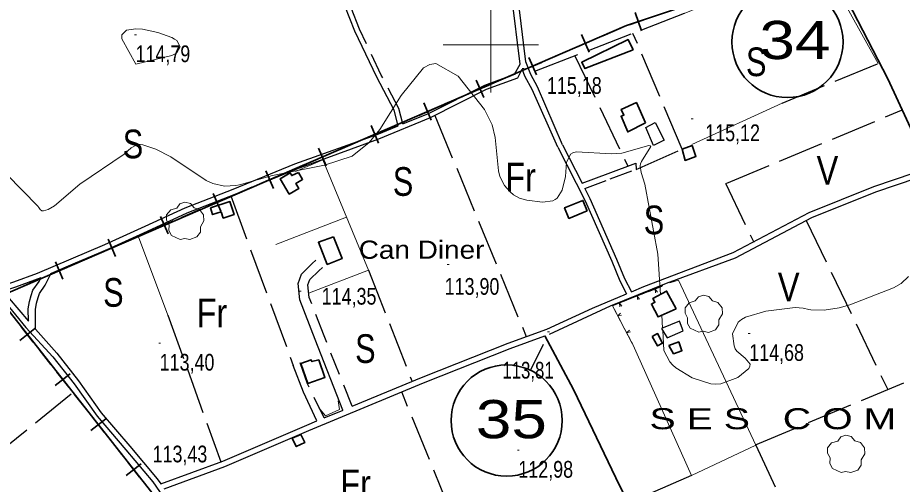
# Model space of a CAD drawing. Extents: x 483840 to 488445, y 4386047 to 4389027.
# Drawn here: x 484752.4 to 485215.3, y 4388270 to 4388514.2 of the extents above; entities that cross this region are included whole.
import ezdxf
from ezdxf.enums import TextEntityAlignment as Align

# ---------------------------------------------------------------- set-up
doc = ezdxf.new("R2010")
doc.units = 0
doc.header["$LTSCALE"] = 4
doc.linetypes.add('LONG_DASHED', pattern=[7.5, 6, -1.5])
doc.linetypes.add('MEDIUM_DASHED', pattern=[4.5, 3, -1.5])
for name, color, linetype, lineweight in [('1', 7, 'Continuous', 13), ('13', 7, 'Continuous', 25), ('21', 7, 'Continuous', 25), ('24', 7, 'Continuous', 13), ('25', 7, 'LONG_DASHED', 25), ('29', 7, 'Continuous', 13), ('34', 7, 'Continuous', 35), ('38', 7, 'Continuous', 25), ('47', 7, 'Continuous', 35), ('51', 7, 'Continuous', 13), ('6', 7, 'Continuous', 35), ('7', 7, 'Continuous', 13), ('9', 7, 'Continuous', 13)]:
    doc.layers.add(name, color=color, linetype=linetype, lineweight=lineweight)
doc.layers.add('31', color=7, linetype='Continuous')
doc.layers.add('5', color=7, linetype='Continuous')

msp = doc.modelspace()

# ---------------------------------------------------------------- linework, layer by layer
at = {"layer": '1'}
for p, q in [((485000, 4388525), (485000, 4388475)), ((484975, 4388500), (485025, 4388500))]:
    msp.add_line(p, q, dxfattribs=at)
at = {"layer": '21'}
for points in [[(485085.2, 4388447.27), (485081.2, 4388456.64), (485086.08, 4388459.28), (485090.67, 4388450.06)], [(485092.34, 4388346.69), (485100.66, 4388350.31), (485098.7, 4388355.4), (485089.4, 4388351.49)]]:
    msp.add_lwpolyline(points, close=True, dxfattribs=at)
at = {"layer": '24'}
for p, q in [((485082.46, 4388370.8), (485089.44, 4388373.55)), ((485063.87, 4388363.49), (485070.85, 4388366.24)), ((485073.17, 4388367.15), (485080.15, 4388369.89)), ((485068.18, 4388354.79), (485064.67, 4388361.42)), ((485072.85, 4388345.96), (485069.34, 4388352.59))]:
    msp.add_line(p, q, dxfattribs=at)
for points in [[(485074.01, 4388343.76), (485063.63, 4388363.4), (485090.09, 4388373.8)], [(485087.19, 4388370.51), (485085.95, 4388372.17), (485086.19, 4388370.12)], [(485077.89, 4388366.86), (485076.66, 4388368.52), (485076.89, 4388366.46)], [(485068.59, 4388363.2), (485067.36, 4388364.87), (485067.6, 4388362.81)], [(485067.94, 4388359.52), (485066.43, 4388358.11), (485068.44, 4388358.58)], [(485072.61, 4388350.69), (485071.09, 4388349.28), (485073.11, 4388349.74)]]:
    msp.add_lwpolyline(points, dxfattribs=at)
at = {"layer": '25'}
for p, q in [((485101.21, 4388516.39), (485020.66, 4388485.07)), ((485044.03, 4388494.16), (485071.69, 4388436.47)), ((485152.45, 4388469.44), (485202.67, 4388490.24)), ((484970.7, 4388463.07), (485018.53, 4388347.26)), ((485123.43, 4388427.6), (485214.94, 4388465.75)), ((485122.74, 4388427.51), (485137.62, 4388396.72)), ((484863.91, 4388420.9), (484896.65, 4388332.19)), ((485165.03, 4388408.01), (485207.74, 4388319.56)), ((484935.95, 4388382.07), (484958.8, 4388323.76)), ((484831.04, 4388358.42), (484858.7, 4388281.74)), ((485138.58, 4388290.73), (485276.3, 4388348.15)), ((484691.81, 4388245.64), (484783.75, 4388320)), ((485104.98, 4388274.62), (485074.29, 4388261.26))]:
    msp.add_line(p, q, dxfattribs=at)
for points in [[(485075.91, 4388438.03), (485076.01, 4388434.79), (485100.13, 4388445.35), (485074.4, 4388505.97)], [(484870.29, 4388214.84), (484979.22, 4388255.21), (484953.38, 4388318.33)], [(485138.71, 4388290.43), (485159.41, 4388245.83), (485093.48, 4388220.32)]]:
    msp.add_lwpolyline(points, dxfattribs=at)
at = {"layer": '29'}
for points in [[(484837.52, 4388398.15), (484832.98, 4388400.27), (484831.57, 4388402.81), (484831.67, 4388405.79), (484830.3, 4388408.2), (484830.34, 4388410.95), (484832.5, 4388413.55), (484835.69, 4388414.55), (484837.34, 4388416.74), (484839.91, 4388417.57), (484842.77, 4388416.92), (484844.72, 4388414.65), (484847.53, 4388413.83), (484849.66, 4388410.98), (484849.9, 4388407.85), (484848.02, 4388404.7), (484848.02, 4388402.02), (484846.2, 4388399.41), (484842.58, 4388398.07), (484839.81, 4388398.7)], [(485108.85, 4388349.53), (485104.31, 4388351.65), (485102.9, 4388354.19), (485103, 4388357.17), (485101.63, 4388359.58), (485101.67, 4388362.33), (485103.83, 4388364.93), (485107.02, 4388365.93), (485108.67, 4388368.12), (485111.24, 4388368.95), (485114.1, 4388368.3), (485116.05, 4388366.03), (485118.86, 4388365.21), (485120.99, 4388362.36), (485121.23, 4388359.23), (485119.35, 4388356.08), (485119.35, 4388353.4), (485117.53, 4388350.79), (485113.91, 4388349.45), (485111.14, 4388350.08)], [(485183.38, 4388276.22), (485178.84, 4388278.34), (485177.43, 4388280.88), (485177.53, 4388283.86), (485176.16, 4388286.27), (485176.2, 4388289.02), (485178.36, 4388291.62), (485181.55, 4388292.62), (485183.2, 4388294.81), (485185.77, 4388295.64), (485188.63, 4388294.99), (485190.58, 4388292.72), (485193.39, 4388291.9), (485195.52, 4388289.05), (485195.76, 4388285.92), (485193.88, 4388282.77), (485193.88, 4388280.09), (485192.06, 4388277.48), (485188.44, 4388276.14), (485185.67, 4388276.77)]]:
    msp.add_lwpolyline(points, close=True, dxfattribs=at)
at = {"layer": '34'}
for p, q in [((485072.45, 4388510.49), (485081.93, 4388513.67)), ((485075.6, 4388516.82), (485078.79, 4388507.34)), ((485047.48, 4388505.3), (485051.45, 4388496.11)), ((485058.65, 4388504.67), (485067.83, 4388508.63)), ((485044.87, 4388498.72), (485054.05, 4388502.69)), ((485031.11, 4388492.78), (485040.29, 4388496.75)), ((485017.34, 4388486.84), (485026.52, 4388490.8)), ((485019.95, 4388493.41), (485023.91, 4388484.23)), ((484992.41, 4388481.53), (484996.38, 4388472.35)), ((485003.58, 4388480.9), (485012.76, 4388484.86)), ((484989.8, 4388474.95), (484998.99, 4388478.92)), ((484976.04, 4388469.01), (484985.22, 4388472.98)), ((484964.88, 4388469.64), (484968.84, 4388460.46)), ((484962.27, 4388463.07), (484971.45, 4388467.03)), ((484948.51, 4388457.13), (484957.69, 4388461.09)), ((484934.73, 4388451.19), (484943.92, 4388455.15)), ((484937.34, 4388457.76), (484941.31, 4388448.58)), ((484920.97, 4388445.25), (484930.15, 4388449.21)), ((484909.81, 4388445.87), (484913.77, 4388436.69)), ((484907.2, 4388439.3), (484916.38, 4388443.26)), ((484893.44, 4388433.36), (484902.62, 4388437.32)), ((484879.66, 4388427.42), (484888.85, 4388431.38)), ((484882.27, 4388433.99), (484886.24, 4388424.81)), ((484854.74, 4388422.11), (484858.7, 4388412.92)), ((484865.9, 4388421.48), (484875.08, 4388425.44)), ((484852.13, 4388415.53), (484861.31, 4388419.5)), ((484838.37, 4388409.59), (484847.55, 4388413.56)), ((484824.6, 4388403.65), (484833.78, 4388407.61)), ((484827.2, 4388410.22), (484831.17, 4388401.04)), ((484799.67, 4388398.34), (484803.63, 4388389.16)), ((484810.83, 4388397.71), (484820.01, 4388401.67)), ((484797.06, 4388391.76), (484806.24, 4388395.73)), ((484783.3, 4388385.82), (484792.48, 4388389.79)), ((484772.13, 4388386.45), (484776.1, 4388377.27)), ((484769.53, 4388379.88), (484778.71, 4388383.84)), ((484755.76, 4388373.94), (484764.94, 4388377.9)), ((484754.37, 4388352.29), (484760.56, 4388344.43)), ((484753.54, 4388345.27), (484761.39, 4388351.45)), ((484763.65, 4388340.5), (484769.84, 4388332.65)), ((484772.93, 4388328.72), (484779.12, 4388320.86)), ((484772.1, 4388321.7), (484779.95, 4388327.88)), ((484782.21, 4388316.93), (484788.4, 4388309.08)), ((484790.66, 4388298.13), (484798.52, 4388304.31)), ((484791.49, 4388305.15), (484797.68, 4388297.29)), ((484800.77, 4388293.36), (484806.96, 4388285.51)), ((484809.22, 4388274.56), (484817.08, 4388280.74)), ((484810.05, 4388281.58), (484816.24, 4388273.72))]:
    msp.add_line(p, q, dxfattribs=at)
for points in [[(484742, 4388368), (485071, 4388510), (485202, 4388554), (485338, 4388632), (485442, 4388724), (485439, 4388753), (485444.8, 4388757.76)], [(484742, 4388368), (484968, 4388081), (484988, 4388018), (485030, 4387786), (485030, 4387747), (484843, 4387760), (484712, 4387762), (484623, 4387793), (484342, 4387807), (484273, 4387819), (484108.44, 4387807.03)]]:
    msp.add_lwpolyline(points, dxfattribs=at)
at = {"layer": '38'}
for p, q in [((484940.47, 4388453.04), (484951.52, 4388457.57)), ((485037.47, 4388447.58), (485047.74, 4388427.5)), ((484912.8, 4388304.73), (484922.8, 4388308.87))]:
    msp.add_line(p, q, dxfattribs=at)
for points in [[(485015.38, 4388489.87), (485011.07, 4388525.18), (485005.15, 4388568.67), (485000, 4388598.29), (484999.53, 4388606.46), (484999.68, 4388610.36), (485000.57, 4388615.38), (485001.38, 4388623.79), (485001.37, 4388629.5), (484995.99, 4388665.8), (484982.61, 4388725.27), (484977.67, 4388757.77)], [(484951.52, 4388457.57), (484949.39, 4388465.73), (484940.36, 4388482.97), (484928.92, 4388507.18), (484918.37, 4388533.79), (484904.08, 4388555.37), (484899.78, 4388573.59), (484895.33, 4388588.74), (484890.42, 4388611.54), (484888.38, 4388617.01)], [(485037.47, 4388447.58), (485024.35, 4388478.07), (485020.87, 4388484.49), (485018.37, 4388491.05), (485014.15, 4388525.57), (485008.22, 4388569.14), (485003.09, 4388598.65), (485002.64, 4388606.49), (485002.78, 4388610.02), (485003.29, 4388612.91)], [(484941.37, 4388450.83), (484968.46, 4388461.94), (484997.8, 4388476.74), (485014.06, 4388482.67), (485016.47, 4388487.3)], [(484953.97, 4388458.58), (484967.47, 4388464.11), (484996.85, 4388478.93), (485012.37, 4388484.59), (485015.38, 4388489.87)], [(485035.03, 4388446.34), (485021.57, 4388476.67), (485018.04, 4388483.19), (485016.47, 4388487.3)], [(484741.2, 4388372.81), (484750.44, 4388375.99), (484762.7, 4388380.54), (484780.4, 4388387.97), (484798.05, 4388395.48), (484819.15, 4388405.1), (484840.07, 4388414.7), (484865.24, 4388424.45), (484897.44, 4388437.64), (484940.47, 4388453.04)], [(484770.03, 4388380.55), (484781.5, 4388385.36), (484799.19, 4388392.89), (484820.32, 4388402.53), (484841.17, 4388412.09), (484866.29, 4388421.82), (484898.45, 4388435), (484941.37, 4388450.83)], [(485035.03, 4388446.34), (485049.33, 4388418.37), (485063.26, 4388386.74), (485067.55, 4388376.55), (485071.05, 4388369.63)], [(485030.66, 4388348.53), (485062.6, 4388363.45), (485091.99, 4388375.2), (485128.12, 4388388.53), (485167.92, 4388409.53), (485201.51, 4388423.01), (485223.17, 4388430.4), (485227.22, 4388434.38), (485228.44, 4388437.61)], [(485047.74, 4388427.5), (485061.44, 4388432.68), (485075.91, 4388438.03)], [(485073.67, 4388370.72), (485080.11, 4388373.42), (485126.9, 4388391.22), (485166.68, 4388412.21), (485200.48, 4388425.77), (485221.58, 4388432.97), (485224.69, 4388436.03), (485225.46, 4388438.06)], [(485049.15, 4388424.75), (485051.81, 4388419.55), (485065.78, 4388387.82), (485070.04, 4388377.72), (485073.67, 4388370.72)], [(484922.6, 4388308.79), (484908.03, 4388345.79), (484900.04, 4388366.48), (484899.13, 4388375.03), (484900.92, 4388379.91), (484906.54, 4388385.47), (484908.49, 4388387.2)], [(484761.66, 4388351.16), (484761.71, 4388361.54), (484762.22, 4388364.87), (484763.12, 4388367.71), (484763.77, 4388369.92), (484766.78, 4388374.13), (484769.99, 4388380.53)], [(484743.7, 4388370.74), (484751.38, 4388373.32), (484764.69, 4388378.26)], [(484757.99, 4388355.29), (484757.97, 4388361.82), (484758.57, 4388365.72), (484759.54, 4388368.8), (484760.36, 4388371.58), (484763.58, 4388376.08), (484764.69, 4388378.26)], [(484743.7, 4388370.74), (484747.92, 4388367.25), (484757.99, 4388355.29)], [(484927.52, 4388310.82), (484963.74, 4388325.81), (485009.08, 4388343.84), (485029.4, 4388351.2), (485053.17, 4388362.16), (485071.05, 4388369.63)], [(484745.93, 4388365.29), (484756.62, 4388352.02), (484770.74, 4388336.73), (484781.96, 4388322.49), (484793.98, 4388305.71), (484808.94, 4388288.11), (484823.15, 4388271.25), (484836.23, 4388252.29)], [(484761.66, 4388351.16), (484772.86, 4388338.54), (484784.18, 4388324.16), (484796.17, 4388307.42), (484811.06, 4388289.91), (484825.37, 4388272.94), (484827.25, 4388270.21)], [(484828.98, 4388267.7), (484860.88, 4388279.4), (484904.81, 4388298.23), (484964.85, 4388323.08), (485010.13, 4388341.08), (485028.24, 4388347.65)], [(484909.03, 4388303.17), (484901.92, 4388318.17), (484896.65, 4388332.19)], [(484827.25, 4388270.21), (484859.79, 4388282.14), (484903.67, 4388300.95), (484909.03, 4388303.17)]]:
    msp.add_lwpolyline(points, dxfattribs=at)
at = {"layer": '38', "linetype": 'MEDIUM_DASHED'}
for points in [[(484953.97, 4388458.58), (484951.85, 4388466.67), (484942.7, 4388484.14), (484931.32, 4388508.22), (484920.7, 4388535.01), (484906.52, 4388556.43), (484902.31, 4388574.26), (484897.87, 4388589.38), (484892.94, 4388612.28), (484890.83, 4388617.92)], [(485049.15, 4388424.75), (485062.52, 4388429.8), (485076.98, 4388435.15)], [(484927.52, 4388310.82), (484912.76, 4388347.62), (484905.01, 4388367.68), (484904.3, 4388374.39), (484905.29, 4388377.1), (484910.01, 4388381.77), (484911.86, 4388383.41)], [(484912.8, 4388304.73), (484904.02, 4388322.59), (484900.19, 4388333.52)]]:
    msp.add_lwpolyline(points, dxfattribs=at)
at = {"layer": '47'}
for points in [[(485074.46, 4388497.29), (485071.83, 4388502.69), (485047.57, 4388490.89), (485049.21, 4388487.5)], [(485080.98, 4388459.19), (485076.23, 4388469.76), (485068.29, 4388466.2), (485069.62, 4388463.22), (485068.13, 4388462.57), (485071.69, 4388454.39)], [(485100.13, 4388445.35), (485105.3, 4388447.23), (485107.37, 4388441.51), (485101.7, 4388439.48)], [(484899.41, 4388433.09), (484901.52, 4388429.57), (484898.05, 4388427.49), (484899.61, 4388424.87), (484894.56, 4388421.87), (484889.78, 4388429.89), (484894.97, 4388433), (484895.86, 4388431.51)], [(484853.31, 4388414.71), (484863.5, 4388417.96), (484865.67, 4388411.12), (484859.95, 4388409.32), (484858.93, 4388412.53), (484854.39, 4388411.11)], [(485050.37, 4388413.16), (485048.19, 4388418.56), (485038.64, 4388414.71), (485040.86, 4388409.17)], [(484917.69, 4388399.44), (484922.21, 4388388.12), (484914.41, 4388385.02), (484909.77, 4388396.67)], [(485096.96, 4388361.85), (485092, 4388371.07), (485084.84, 4388367.24), (485085.87, 4388365.29), (485084.05, 4388364.34), (485087.55, 4388357.61)], [(485084.38, 4388347.35), (485087.23, 4388348.86), (485089.9, 4388343.81), (485087.27, 4388342.44)], [(485093.09, 4388342.64), (485098.34, 4388344.53), (485100.01, 4388339.87), (485095.64, 4388338.32)], [(484909.92, 4388335.07), (484913.16, 4388325.84), (484904.29, 4388322.73), (484900.62, 4388333.19), (484906.04, 4388335.09), (484906.34, 4388334.21)], [(484896.11, 4388294.16), (484898.22, 4388289.74), (484902.66, 4388291.86), (484900.66, 4388296.02)]]:
    msp.add_lwpolyline(points, close=True, dxfattribs=at)
at = {"layer": '51'}
for p, q in [((485105.15, 4388447.83), (485152.45, 4388469.44)), ((484887.47, 4388395.57), (484924.52, 4388409.73)), ((484831.04, 4388358.42), (484815.67, 4388399.57))]:
    msp.add_line(p, q, dxfattribs=at)
for points in [[(485202.67, 4388490.22), (485172.05, 4388545.53), (485101.21, 4388516.39)], [(484897.76, 4388433.61), (484912.08, 4388439.79), (484935.95, 4388382.07), (484905.13, 4388370.19)], [(485073.59, 4388344.71), (485104.98, 4388274.62), (485138.71, 4388290.43), (485098.14, 4388376.78), (485093.64, 4388375.5)], [(484910.07, 4388309.95), (484913.5, 4388305.82), (484920.77, 4388309.2), (484920.05, 4388313.72)]]:
    msp.add_lwpolyline(points, dxfattribs=at)
at = {"layer": '6', "lineweight": 25}
msp.add_line((485020.88, 4388329.89), (485027.62, 4388343.37), dxfattribs=at)
at = {"layer": '6'}
for points in [[(485224.04, 4388447.11), (485207.78, 4388482.2), (485189.48, 4388517.58), (485178.95, 4388536.92), (485175.21, 4388541.77), (485174.76, 4388545.72), (485175.43, 4388546.79)], [(485028.24, 4388347.65), (485043.19, 4388319.65), (485065.47, 4388273.4), (485082.48, 4388238.78), (485092.64, 4388215.91), (485107.46, 4388190.21), (485118.68, 4388162.55), (485126.48, 4388148.04)]]:
    msp.add_lwpolyline(points, dxfattribs=at)
for centre in [(485155.26, 4388501.45), (485008.3, 4388303.36)]:
    msp.add_circle(centre, 29.1, dxfattribs=at)
at = {"layer": '7'}
for p, q in [((484813.58, 4388505.27), (484814.58, 4388505.27)), ((485016.37, 4388487.59), (485017.37, 4388487.59)), ((485104.85, 4388461.18), (485105.85, 4388461.18)), ((484977.23, 4388385.06), (484978.23, 4388385.06)), ((484899.76, 4388370.98), (484900.76, 4388370.98)), ((485029.64, 4388349.82), (485030.64, 4388349.82)), ((485134.74, 4388348.94), (485135.74, 4388348.94)), ((484826.22, 4388343.86), (484827.22, 4388343.86)), ((485013.92, 4388287.83), (485014.92, 4388287.83))]:
    msp.add_line(p, q, dxfattribs=at)
at = {"layer": '9'}
msp.add_line((485089.88, 4388351.69), (485089.46, 4388358.47), dxfattribs=at)
msp.add_lwpolyline([(484814.3, 4388489.76), (484806.96, 4388503.02), (484806.84, 4388504.17), (484806.95, 4388505.17), (484809.3, 4388507.6), (484814.18, 4388508.33), (484817.76, 4388508.08), (484825.81, 4388506.42), (484833.11, 4388503.79), (484834.5, 4388503), (484835.62, 4388502.17), (484837.4, 4388498.94), (484835.64, 4388495.82), (484834.52, 4388495.06), (484833.13, 4388494.35)], close=True, dxfattribs=at)
for points in [[(485044.6, 4388443.9), (485042.96, 4388443.43), (485041.64, 4388442.74), (485039.55, 4388438.36), (485039, 4388431.01), (485037.3, 4388423.97), (485034.65, 4388419.72), (485033.6, 4388418.95), (485032.43, 4388418.36), (485027.05, 4388417.67), (485018.79, 4388418.74), (485015, 4388419.8), (485011.85, 4388421.54), (485010.15, 4388422.98), (485007.15, 4388426.42), (485004.78, 4388431.02), (485003.96, 4388434.09), (485002.35, 4388451.43), (485000.65, 4388458.18), (484996.66, 4388466.13), (484982.98, 4388483.64), (484971.25, 4388490.17), (484968.01, 4388489.59), (484964.76, 4388487.97), (484953.02, 4388473.49), (484941.95, 4388455.7), (484936.41, 4388448.82), (484927.45, 4388441.76), (484912.97, 4388437.01), (484885.76, 4388431.61), (484868.42, 4388426.65), (484866.63, 4388426.35), (484860.59, 4388426.02), (484854.61, 4388427.32), (484851.04, 4388428.94), (484832.53, 4388441.32), (484824.76, 4388445.32), (484817.95, 4388447.63), (484816.45, 4388447.82), (484815.12, 4388447.81), (484811.72, 4388446.14), (484808.11, 4388442.71), (484784.95, 4388427.1), (484771.6, 4388415.64), (484768.29, 4388413.78), (484765.95, 4388413.15), (484765.46, 4388413.12), (484765.05, 4388413.15), (484764.14, 4388413.77), (484763.46, 4388414.88), (484762.9, 4388415.57), (484730.29, 4388448.77)], [(485088.78, 4388369.35), (485087.47, 4388390.38), (485080.65, 4388427.14), (485078.64, 4388433.08), (485078.1, 4388436.62), (485078.37, 4388437.72), (485078.81, 4388438.88), (485083.81, 4388446.83), (485083.47, 4388447.19), (485082.77, 4388447.3), (485068.6, 4388443.36), (485063.41, 4388442.93), (485044.6, 4388443.9)], [(485218.64, 4388378.8), (485214.76, 4388375.08), (485210.67, 4388372.73), (485187.84, 4388363.83), (485182.36, 4388362.36), (485174.47, 4388361.19), (485167.51, 4388361.3), (485166.39, 4388361.42), (485163.47, 4388362.17), (485159.26, 4388362.53), (485143.98, 4388360.63), (485133.24, 4388357.47), (485131.16, 4388356.25), (485129.46, 4388354.88), (485126.55, 4388348.68), (485127.31, 4388342.38), (485127.92, 4388340.95), (485128.72, 4388339.65), (485133.06, 4388336.09), (485135.81, 4388332.9), (485135.61, 4388331.83), (485134.99, 4388330.68), (485129.24, 4388325.86), (485120.41, 4388322.58), (485117.84, 4388322.4), (485115.22, 4388322.53), (485105.31, 4388325.65), (485096.81, 4388330.99), (485095.09, 4388332.53), (485093.63, 4388334.09), (485090.62, 4388339.95), (485089.95, 4388350.59)]]:
    msp.add_lwpolyline(points, dxfattribs=at)

# ---------------------------------------------------------------- texts
at = {"layer": '13', "width": 1.25}
for s, p in [('34', (485159.16, 4388492.5)), ('35', (485010.76, 4388294.1))]:
    msp.add_text(s, height=20, dxfattribs=at).set_placement(p, align=Align.CENTER)
at = {"layer": '31'}
for s, width, p in [('S', 0.8, (485138.89, 4388483.58)), ('S', 0.8, (484812.74, 4388440.59)), ('V', 0.85, (485176.17, 4388426.8)), ('S', 0.8, (484954.08, 4388420.95)), ('Fr', 0.85, (485015.58, 4388423.22)), ('S', 0.8, (485085.38, 4388400.85)), ('V', 0.85, (485155.9, 4388365.71)), ('S', 0.8, (484802.48, 4388362.9)), ('Fr', 0.85, (484854.09, 4388352.18)), ('S', 0.8, (484934.36, 4388333.52)), ('Fr', 0.85, (484929.21, 4388262.69))]:
    msp.add_text(s, height=15, dxfattribs=dict(at, width=width)).set_placement(p, align=Align.CENTER)
at = {"layer": '5'}
for s, height, width, p in [('Can Diner', 9.5, 1.15, (484996.66, 4388388.02)), ('S E S   C O M U N E S', 10.99, 1.4, (485292.24, 4388298.83))]:
    msp.add_text(s, height=height, dxfattribs=dict(at, width=width)).set_placement(p, align=Align.RIGHT)
at = {"layer": '7'}
for s, width, p in [('114,79', 0.8, (484814.08, 4388490.9)), ('115,18', 0.8, (485029.39, 4388474.31)), ('115,12', 0.8, (485112.22, 4388449.57)), ('113,90', 0.8, (484975.86, 4388369.18)), ('114,35', 0.8, (484911.51, 4388364.02)), ('114,68', 0.8, (485135.24, 4388334.57)), ('113,40', 0.8, (484826.72, 4388329.49)), ('113,81', 0.75, (485006.05, 4388325.34)), ('113,43', 0.8, (484823.01, 4388281.49)), ('112,98', 0.8, (485014.42, 4388273.46))]:
    msp.add_text(s, height=8.75, dxfattribs=dict(at, width=width)).set_placement(p)

doc.saveas('drawing.dxf')
